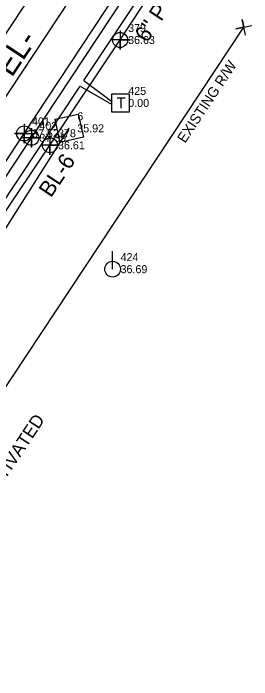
# Model space of a CAD drawing. Extents: x 2603627 to 2605187, y 896619 to 899063.
# Drawn here: x 2605010.8 to 2605085.2, y 898680.4 to 898888.5 of the extents above; entities that cross this region are included whole.
import ezdxf

# ---------------------------------------------------------------- set-up
doc = ezdxf.new("R2010")
doc.units = 0
for name, color, linetype in [('CTL Supplemental Horizontal and Vertical CELL', 7, 'Continuous'), ('CTL Supplemental Horizontal and Vertical Cogo Elevation', 7, 'Continuous'), ('CTL Supplemental Horizontal and Vertical Cogo Number', 7, 'Continuous'), ('CTL Supplemental Horizontal and Vertical Text', 7, 'Continuous'), ('Exist Horizontal Alignment', 7, 'Continuous'), ('Exist Horizontal Alignment Direction Label', 7, 'Continuous'), ('Exist Horizontal Baseline Alignment', 7, 'Continuous'), ('Exist Other Culture Area Outline Text', 7, 'Continuous'), ('Exist Property Corner CELL', 7, 'Continuous'), ('Exist Right of Way Line', 7, 'Continuous'), ('Exist Right of Way Line Text', 7, 'Continuous'), ('Exist Roads EOP', 7, 'Continuous'), ('Exist Roads EOP Cogo Elevation', 7, 'Continuous'), ('Exist Roads EOP Cogo Number', 7, 'Continuous'), ('Exist Roads EOP Cogo Point CELL', 7, 'Continuous'), ('Exist Roads EOT', 7, 'Continuous'), ('Exist Roads EOT Cogo Elevation', 7, 'Continuous'), ('Exist Roads EOT Cogo Number', 7, 'Continuous'), ('Exist Roads EOT Cogo Point CELL', 7, 'Continuous'), ('Exist Utilities Power Pole CELL', 7, 'Continuous'), ('Exist Utilities Power Pole Cogo Elevation', 7, 'Continuous'), ('Exist Utilities Power Pole Cogo Number', 7, 'Continuous'), ('Exist Utilities Telephone Pedestal CELL', 7, 'Continuous'), ('Exist Utilities Telephone Pedestal Cogo Elevation', 7, 'Continuous'), ('Exist Utilities Telephone Pedestal Cogo Number', 7, 'Continuous'), ('Exist Utilities Telephone UG Cable SUE LOS C', 7, 'Continuous'), ('Exist Utilities Water UG Line SUE LOS B', 7, 'Continuous'), ('Exist Utilities Water UG Line SUE LOS B Cogo Elevation', 7, 'Continuous'), ('Exist Utilities Water UG Line SUE LOS B Cogo Number', 7, 'Continuous'), ('Exist Utilities Water UG Line SUE LOS B Cogo Point CELL', 7, 'Continuous'), ('Exist Utilities Water UG Line SUE LOS B Text', 7, 'Continuous')]:
    doc.layers.add(name, color=color, linetype=linetype)

# ---------------------------------------------------------------- blocks, each defined once
blk = doc.blocks.new('EXIST UTILITIES WATER UG LINE SUE LOS B COGO POINT')
at = {"layer": 'Exist Utilities Water UG Line SUE LOS B Cogo Point CELL'}
blk.add_lwpolyline([(0, 0.06), (0, -0.06), (0, 0), (0.06, 0), (-0.06, 0)], dxfattribs=at)
blk.add_circle((0, 0), 0.0469, dxfattribs=at)
blk = doc.blocks.new('EXIST ROADS EOT COGO POINT')
at = {"layer": 'Exist Roads EOT Cogo Point CELL'}
blk.add_lwpolyline([(0, 0.06), (0, -0.06), (0, 0), (-0.06, 0), (0.06, 0)], dxfattribs=at)
blk.add_circle((0, 0), 0.0469, dxfattribs=at)
blk = doc.blocks.new('EXIST ROADS EOP COGO POINT')
at = {"layer": 'Exist Roads EOP Cogo Point CELL'}
blk.add_lwpolyline([(0, 0.06), (0, -0.06), (0, 0), (0.06, 0), (-0.06, 0)], dxfattribs=at)
blk.add_circle((0, 0), 0.0469, dxfattribs=at)
blk = doc.blocks.new('EXIST UTILITIES TELEPHONE PEDESTAL')
at = {"layer": 'Exist Utilities Telephone Pedestal CELL'}
blk.add_line((0, 0), (0, 0), dxfattribs=at)
blk.add_lwpolyline([(-0.0545, -0.0565), (0.0574, -0.0565), (0.0574, 0.0554), (-0.0545, 0.0554), (-0.0545, -0.0565)], dxfattribs=at)
blk.add_text('T', height=0.0684, dxfattribs=at).set_placement((-0.0226, -0.0343))
blk = doc.blocks.new('CTL SUPPLEMENTAL HORIZONTAL AND VERTICAL')
at = {"layer": 'CTL Supplemental Horizontal and Vertical CELL'}
blk.add_line((0, 0), (0, 0), dxfattribs=at)
blk.add_lwpolyline([(-0.1043, 0.0004), (0.0005, 0.1052), (0.1055, 0.0002), (0.0007, -0.1047)], close=True, dxfattribs=at)

msp = doc.modelspace()

# ---------------------------------------------------------------- linework, layer by layer
at = {"layer": 'Exist Horizontal Alignment'}
msp.add_line((2604681.44, 898368.79), (2605041.11, 898911.74), dxfattribs=at)
at = {"layer": 'Exist Horizontal Baseline Alignment'}
msp.add_line((2604793.6, 898483.9), (2605028.26, 898852.56), dxfattribs=at)
at = {"layer": 'Exist Property Corner CELL'}
msp.add_line((2605082.79, 898884.13), (2605082.79, 898884.13), dxfattribs=at)
msp.add_lwpolyline([(2605083.29, 898881.68), (2605082.29, 898886.58), (2605082.79, 898884.13), (2605080.34, 898883.63), (2605085.24, 898884.63)], dxfattribs=at)
at = {"layer": 'Exist Right of Way Line'}
msp.add_line((2604723.13, 898341.18), (2605082.79, 898884.13), dxfattribs=at)
at = {"layer": 'Exist Roads EOP'}
msp.add_lwpolyline([(2604713.86, 898392.44), (2604740.28, 898432.25), (2604768.45, 898474.26), (2604797.27, 898517.92), (2604823.93, 898558.47), (2604851.31, 898599.84), (2604878.52, 898641.09), (2604906.84, 898683.65), (2604934.68, 898725.71), (2604962.63, 898767.92), (2604989.32, 898808.49), (2605016.42, 898849.59), (2605045.34, 898893.33), (2605052.55, 898904.16)], dxfattribs=at)
at = {"layer": 'Exist Roads EOT'}
for points in [[(2604580.65, 898235.67), (2604609.23, 898279.3), (2604636.66, 898320.72), (2604665.18, 898363.91), (2604693.37, 898406.36), (2604719.95, 898446.05), (2604748, 898488.34), (2604776.15, 898530.84), (2604803.5, 898572.3), (2604830.95, 898613.91), (2604857.58, 898654.47), (2604886.02, 898697.38), (2604913.86, 898739.33), (2604942.03, 898781.72), (2604969.06, 898822.38), (2604996.07, 898863.44), (2605024.73, 898906.73), (2605032, 898917.78)], [(2604598.04, 898223.4), (2604627.23, 898267.23), (2604654.64, 898308.57), (2604683.28, 898352.01), (2604711.27, 898394.14), (2604737.98, 898434.05), (2604766.04, 898475.94), (2604794.96, 898519.26), (2604821.61, 898559.82), (2604848.89, 898601.4), (2604876.12, 898642.73), (2604904.4, 898685.35), (2604932.33, 898727.23), (2604960.29, 898769.49), (2604987.32, 898810.19), (2605014.12, 898850.95), (2605043.08, 898894.89), (2605050.2, 898905.72)]]:
    msp.add_lwpolyline(points, dxfattribs=at)
at = {"layer": 'Exist Utilities Power Pole CELL'}
for q in [(2605041.78, 898814.21), (2605041.78, 898808.58)]:
    msp.add_line((2605041.78, 898808.58), q, dxfattribs=at)
msp.add_circle((2605041.78, 898808.58), 2.45, dxfattribs=at)
at = {"layer": 'Exist Utilities Telephone UG Cable SUE LOS C'}
for p, q in [((2605032.82, 898867.49), (2605055.78, 898902.01)), ((2605032.82, 898867.49), (2605041.46, 898860.98)), ((2604850.74, 898593.69), (2605031.63, 898865.69)), ((2605031.63, 898865.69), (2605041.46, 898860.05))]:
    msp.add_line(p, q, dxfattribs=at)
at = {"layer": 'Exist Utilities Water UG Line SUE LOS B'}
msp.add_lwpolyline([(2604590.41, 898183.07), (2604608.13, 898210.78), (2604631.33, 898247.72), (2604631.98, 898248.77), (2604637.93, 898260.9), (2604650.01, 898281.75), (2604670.13, 898312.66), (2604706.14, 898370.49), (2604744.2, 898428.79), (2604775.85, 898478.14), (2604817.62, 898541.22), (2604844.76, 898580.18), (2604876.2, 898627.22), (2604907.55, 898675.15), (2604931.69, 898711.47), (2604963.51, 898758.63), (2604991.08, 898800.9), (2605022.23, 898847.26), (2605044.13, 898880.13), (2605057.71, 898900.74)], dxfattribs=at)

# ---------------------------------------------------------------- block references
at = {"layer": 'CTL Supplemental Horizontal and Vertical CELL', "xscale": 50, "yscale": 50, "rotation": 57.62740702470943}
msp.add_blockref('CTL SUPPLEMENTAL HORIZONTAL AND VERTICAL', (2605028.26, 898852.56), dxfattribs=at)
at = {"layer": 'Exist Roads EOP Cogo Point CELL', "xscale": 50, "yscale": 50}
msp.add_blockref('EXIST ROADS EOP COGO POINT', (2605016.42, 898849.59), dxfattribs=at)
at = {"layer": 'Exist Roads EOT Cogo Point CELL', "xscale": 50, "yscale": 50}
msp.add_blockref('EXIST ROADS EOT COGO POINT', (2605014.12, 898850.95), dxfattribs=at)
at = {"layer": 'Exist Utilities Telephone Pedestal CELL', "xscale": 50, "yscale": 50}
msp.add_blockref('EXIST UTILITIES TELEPHONE PEDESTAL', (2605044.18, 898860.48), dxfattribs=at)
at = {"layer": 'Exist Utilities Water UG Line SUE LOS B Cogo Point CELL', "xscale": 50, "yscale": 50}
for p in [(2605044.13, 898880.13), (2605022.23, 898847.26)]:
    msp.add_blockref('EXIST UTILITIES WATER UG LINE SUE LOS B COGO POINT', p, dxfattribs=at)

# ---------------------------------------------------------------- texts
at = {"layer": 'CTL Supplemental Horizontal and Vertical Cogo Elevation'}
msp.add_text('35.92', height=2.5, dxfattribs=at).set_placement((2605030.76, 898851.31))
at = {"layer": 'CTL Supplemental Horizontal and Vertical Cogo Number'}
msp.add_text('6', height=2.5, dxfattribs=at).set_placement((2605030.76, 898855.06))
at = {"layer": 'CTL Supplemental Horizontal and Vertical Text'}
msp.add_text('BL-6', height=5, rotation=56.4094, dxfattribs=at).set_placement((2605022.54, 898830.67))
at = {"layer": 'Exist Horizontal Alignment Direction Label'}
msp.add_text('-EL-', height=7, rotation=56.4785, dxfattribs=at).set_placement((2605008.6, 898865.62))
at = {"layer": 'Exist Other Culture Area Outline Text'}
msp.add_text('CULTIVATED', height=4, rotation=56.4786, dxfattribs=at).set_placement((2605002.37, 898733.86))
at = {"layer": 'Exist Right of Way Line Text'}
msp.add_text('EXISTING R/W', height=3.2, rotation=56.4785, dxfattribs=at).set_placement((2605064.42, 898847.71))
at = {"layer": 'Exist Roads EOP Cogo Elevation'}
msp.add_text('37.39', height=2.5, dxfattribs=at).set_placement((2605018.92, 898848.34))
at = {"layer": 'Exist Roads EOP Cogo Number'}
msp.add_text('402', height=2.5, dxfattribs=at).set_placement((2605018.92, 898852.09))
at = {"layer": 'Exist Roads EOT Cogo Elevation'}
msp.add_text('37.52', height=2.5, dxfattribs=at).set_placement((2605016.62, 898849.7))
at = {"layer": 'Exist Roads EOT Cogo Number'}
msp.add_text('401', height=2.5, dxfattribs=at).set_placement((2605016.62, 898853.45))
at = {"layer": 'Exist Utilities Power Pole Cogo Elevation'}
msp.add_text('36.69', height=2.5, dxfattribs=at).set_placement((2605044.28, 898807.33))
at = {"layer": 'Exist Utilities Power Pole Cogo Number'}
msp.add_text('424', height=2.5, dxfattribs=at).set_placement((2605044.28, 898811.08))
at = {"layer": 'Exist Utilities Telephone Pedestal Cogo Elevation'}
msp.add_text('0.00', height=2.5, dxfattribs=at).set_placement((2605046.68, 898859.23))
at = {"layer": 'Exist Utilities Telephone Pedestal Cogo Number'}
msp.add_text('425', height=2.5, dxfattribs=at).set_placement((2605046.68, 898862.98))
at = {"layer": 'Exist Utilities Water UG Line SUE LOS B Cogo Elevation'}
for s, p in [('36.63', (2605046.63, 898878.88)), ('36.61', (2605024.73, 898846.01))]:
    msp.add_text(s, height=2.5, dxfattribs=at).set_placement(p)
at = {"layer": 'Exist Utilities Water UG Line SUE LOS B Cogo Number'}
for s, p in [('379', (2605046.63, 898882.63)), ('378', (2605024.73, 898849.76))]:
    msp.add_text(s, height=2.5, dxfattribs=at).set_placement(p)
at = {"layer": 'Exist Utilities Water UG Line SUE LOS B Text'}
msp.add_text('6" PVC', height=5, rotation=56.6068, dxfattribs=at).set_placement((2605052.59, 898879.06))

doc.saveas('drawing.dxf')
